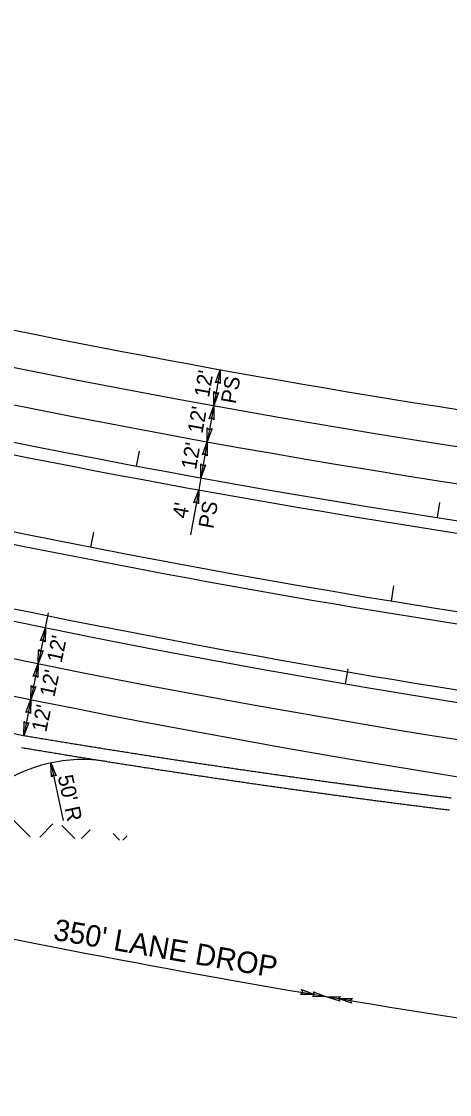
# Model space of a CAD drawing. Extents: x 2389099 to 2405615, y 552200 to 573532.
# Drawn here: x 2399152.7 to 2399293, y 552297.8 to 552649 of the extents above; entities that cross this region are included whole.
import ezdxf

# ---------------------------------------------------------------- set-up
doc = ezdxf.new("R2010")
doc.units = 0
for name, color, linetype in [('Old_Level_22', 7, 'Continuous'), ('Prop Cable Guiderail Double Face', 7, 'Continuous'), ('Prop Dimension', 7, 'Continuous'), ('Prop Dimension Text', 7, 'Continuous'), ('Prop EOT', 7, 'Continuous'), ('Prop Hatching', 7, 'Continuous'), ('Prop Horizontal Alignment', 7, 'Continuous'), ('Prop Horizontal Alignment Tick Small', 7, 'Continuous'), ('Prop Lane Lines', 7, 'Continuous')]:
    doc.layers.add(name, color=color, linetype=linetype)

msp = doc.modelspace()

# ---------------------------------------------------------------- linework, layer by layer
at = {"layer": 'Prop Cable Guiderail Double Face'}
msp.add_arc((2399806.57, 555716.05), 3304, 257.63644, 265.28379, dxfattribs=at)
at = {"layer": 'Prop Dimension'}
for p, q in [((2399217.86, 552535.06), (2399215.75, 552523.25)), ((2399215.75, 552523.25), (2399213.63, 552511.43)), ((2399213.63, 552511.43), (2399211.52, 552499.62)), ((2399211.52, 552499.62), (2399210.81, 552495.68)), ((2399210.81, 552495.68), (2399208.1, 552480.93)), ((2399160.62, 552450.59), (2399158.24, 552438.82)), ((2399158.24, 552438.82), (2399155.86, 552427.06)), ((2399155.86, 552427.06), (2399153.48, 552415.3)), ((2399162.35, 552406.3), (2399166.42, 552387.43))]:
    msp.add_line(p, q, dxfattribs=at)
for points in [[(2399216.3, 552530.77), (2399217.86, 552535.06), (2399217.85, 552530.46), (2399217.16, 552531.17)], [(2399217.3, 552527.54), (2399215.75, 552523.25), (2399215.76, 552527.84), (2399216.44, 552527.13)], [(2399214.19, 552518.95), (2399215.75, 552523.25), (2399215.74, 552518.65), (2399215.05, 552519.36)], [(2399215.19, 552515.73), (2399213.63, 552511.43), (2399213.64, 552516.03), (2399214.33, 552515.32)], [(2399212.08, 552507.14), (2399213.63, 552511.43), (2399213.62, 552506.84), (2399212.94, 552507.55)], [(2399213.08, 552503.91), (2399211.52, 552499.62), (2399211.53, 552504.22), (2399212.22, 552503.51)], [(2399209.24, 552491.4), (2399210.81, 552495.68), (2399210.78, 552491.09), (2399210.1, 552491.8)], [(2399158.97, 552446.33), (2399160.62, 552450.59), (2399160.51, 552445.99), (2399159.84, 552446.71)], [(2399159.89, 552443.08), (2399158.24, 552438.82), (2399158.35, 552443.42), (2399159.02, 552442.7)], [(2399156.59, 552434.57), (2399158.24, 552438.82), (2399158.13, 552434.23), (2399157.46, 552434.95)], [(2399157.51, 552431.32), (2399155.86, 552427.06), (2399155.97, 552431.66), (2399156.64, 552430.93)], [(2399154.21, 552422.81), (2399155.86, 552427.06), (2399155.75, 552422.47), (2399155.08, 552423.19)], [(2399155.13, 552419.56), (2399153.48, 552415.3), (2399153.59, 552419.9), (2399154.26, 552419.17)], [(2399162.54, 552401.74), (2399162.35, 552406.3), (2399164.09, 552402.04), (2399163.18, 552402.44)], [(2399244.52, 552332.11), (2399248.8, 552330.53), (2399244.2, 552330.57), (2399244.92, 552331.25)], [(2399248.4, 552331.39), (2399252.68, 552329.8), (2399248.09, 552329.84), (2399248.8, 552330.53)], [(2399257, 552328.31), (2399252.68, 552329.8), (2399257.28, 552329.86), (2399256.58, 552329.16)], [(2399260.9, 552327.69), (2399256.58, 552329.16), (2399261.17, 552329.25), (2399260.48, 552328.55)]]:
    msp.add_lwpolyline(points, close=True, dxfattribs=at)
msp.add_arc((2399820.18, 555707.47), 3424.97, 258.5517, 264.5865, dxfattribs=at)
at = {"layer": 'Prop EOT'}
for centre, radius, start, end in [((2399792.96, 555724.63), 3253, 240.16192, 265.26734), ((2399792.96, 555724.63), 3241, 256.84167, 265.26734), ((2399820.18, 555707.47), 3359, 249.83254, 258.5517), ((2399792.96, 555724.63), 3281, 256.78262, 265.26734), ((2399820.18, 555707.47), 3319, 256.69858, 263.72436), ((2399172.89, 552357.42), 50, 80.9773, 168.0231)]:
    msp.add_arc(centre, radius, start, end, dxfattribs=at)
for points in [[(2399153.48, 552415.3), (2399154.42, 552415.14), (2399155.36, 552414.99), (2399156.31, 552414.83), (2399157.25, 552414.67), (2399158.19, 552414.51), (2399159.14, 552414.36), (2399160.08, 552414.2), (2399161.03, 552414.05), (2399161.97, 552413.89), (2399162.91, 552413.73), (2399163.86, 552413.58), (2399164.8, 552413.43), (2399165.75, 552413.27), (2399166.69, 552413.12), (2399167.64, 552412.96), (2399168.58, 552412.81), (2399169.52, 552412.65), (2399170.47, 552412.5), (2399171.41, 552412.35), (2399172.36, 552412.2), (2399173.29, 552412.04), (2399174.24, 552411.89), (2399175.19, 552411.74), (2399176.13, 552411.59), (2399177.08, 552411.44), (2399178.02, 552411.29), (2399178.97, 552411.13), (2399179.91, 552410.98), (2399180.85, 552410.83), (2399181.8, 552410.68), (2399182.74, 552410.53), (2399183.69, 552410.38), (2399184.64, 552410.23), (2399185.58, 552410.09), (2399186.53, 552409.94), (2399187.46, 552409.79), (2399188.41, 552409.64), (2399189.36, 552409.49), (2399190.3, 552409.35), (2399191.25, 552409.2), (2399192.19, 552409.05), (2399193.14, 552408.9), (2399194.09, 552408.76), (2399195.03, 552408.61), (2399195.98, 552408.46), (2399196.92, 552408.32), (2399197.86, 552408.17), (2399198.81, 552408.03), (2399199.75, 552407.88), (2399200.7, 552407.74), (2399201.64, 552407.6), (2399202.59, 552407.45), (2399203.54, 552407.31), (2399204.48, 552407.16), (2399205.43, 552407.02), (2399206.37, 552406.88), (2399207.32, 552406.73), (2399208.26, 552406.59), (2399209.21, 552406.45), (2399210.16, 552406.31), (2399211.1, 552406.17), (2399212.05, 552406.03), (2399212.99, 552405.89), (2399213.94, 552405.74), (2399214.89, 552405.6), (2399215.83, 552405.46), (2399216.78, 552405.32), (2399217.72, 552405.18), (2399218.67, 552405.04), (2399219.62, 552404.9), (2399220.56, 552404.77), (2399221.51, 552404.63), (2399222.45, 552404.49), (2399223.4, 552404.35)], [(2399152.82, 552411.36), (2399153.76, 552411.2), (2399154.7, 552411.04), (2399155.65, 552410.88), (2399156.59, 552410.73), (2399157.54, 552410.57), (2399158.49, 552410.41), (2399159.43, 552410.26), (2399160.38, 552410.1), (2399161.32, 552409.94), (2399162.27, 552409.79), (2399163.21, 552409.63), (2399164.15, 552409.48), (2399165.1, 552409.32), (2399166.04, 552409.17), (2399166.99, 552409.01), (2399167.94, 552408.86), (2399168.88, 552408.71), (2399169.83, 552408.55), (2399170.77, 552408.4), (2399171.72, 552408.25), (2399172.66, 552408.09), (2399173.61, 552407.94), (2399174.56, 552407.79), (2399175.5, 552407.64), (2399176.45, 552407.49), (2399177.39, 552407.34), (2399178.33, 552407.18), (2399179.29, 552407.03), (2399180.23, 552406.88), (2399181.18, 552406.73), (2399182.12, 552406.58), (2399183.06, 552406.43), (2399184.01, 552406.28), (2399184.95, 552406.14), (2399185.9, 552405.99), (2399186.84, 552405.84), (2399187.79, 552405.69), (2399188.75, 552405.54), (2399189.69, 552405.39), (2399190.64, 552405.25), (2399191.58, 552405.1), (2399192.52, 552404.95), (2399193.48, 552404.8), (2399194.42, 552404.66), (2399195.37, 552404.51), (2399196.31, 552404.37), (2399197.26, 552404.22), (2399198.21, 552404.07), (2399199.15, 552403.93), (2399200.1, 552403.79), (2399201.04, 552403.64), (2399201.99, 552403.5), (2399202.94, 552403.35), (2399203.88, 552403.21), (2399204.83, 552403.07), (2399205.77, 552402.92), (2399206.72, 552402.78), (2399207.66, 552402.64), (2399208.61, 552402.49), (2399209.56, 552402.35), (2399210.51, 552402.21), (2399211.46, 552402.07), (2399212.4, 552401.93), (2399213.35, 552401.79), (2399214.3, 552401.65), (2399215.24, 552401.51), (2399216.19, 552401.37), (2399217.13, 552401.23), (2399218.08, 552401.09), (2399219.03, 552400.95), (2399219.98, 552400.81), (2399220.93, 552400.67), (2399221.87, 552400.53), (2399222.82, 552400.39)], [(2399223.4, 552404.35), (2399224.35, 552404.21), (2399225.29, 552404.08), (2399226.24, 552403.94), (2399227.18, 552403.8), (2399228.13, 552403.66), (2399229.08, 552403.53), (2399230.02, 552403.39), (2399230.97, 552403.25), (2399231.91, 552403.12), (2399232.86, 552402.98), (2399233.81, 552402.85), (2399234.75, 552402.71), (2399235.7, 552402.58), (2399236.64, 552402.45), (2399237.59, 552402.31), (2399238.54, 552402.18), (2399239.48, 552402.04), (2399240.43, 552401.91), (2399241.37, 552401.78), (2399242.32, 552401.65), (2399243.27, 552401.51), (2399244.22, 552401.38), (2399245.17, 552401.25), (2399246.11, 552401.12), (2399247.06, 552400.99), (2399248, 552400.86), (2399248.95, 552400.72), (2399249.9, 552400.59), (2399250.84, 552400.46), (2399251.79, 552400.33), (2399252.73, 552400.2), (2399253.68, 552400.07), (2399254.64, 552399.94), (2399255.58, 552399.82), (2399256.53, 552399.69), (2399257.47, 552399.56), (2399258.42, 552399.43), (2399259.37, 552399.3), (2399260.31, 552399.18), (2399261.26, 552399.05), (2399262.21, 552398.92), (2399263.16, 552398.79), (2399264.11, 552398.67), (2399265.05, 552398.54), (2399266, 552398.42), (2399266.94, 552398.29), (2399267.89, 552398.17), (2399268.84, 552398.04), (2399269.79, 552397.92), (2399270.74, 552397.79), (2399271.68, 552397.67), (2399272.63, 552397.54), (2399273.58, 552397.42), (2399274.52, 552397.3), (2399275.48, 552397.17), (2399276.42, 552397.05), (2399277.37, 552396.93), (2399278.31, 552396.8), (2399279.26, 552396.68), (2399280.21, 552396.56), (2399281.16, 552396.44), (2399282.11, 552396.32), (2399283.05, 552396.2), (2399284, 552396.08), (2399284.95, 552395.95), (2399285.9, 552395.84), (2399286.85, 552395.71), (2399287.79, 552395.6), (2399288.74, 552395.48), (2399289.69, 552395.36), (2399290.64, 552395.24), (2399291.59, 552395.12), (2399292.53, 552395), (2399293.48, 552394.88)], [(2399222.82, 552400.39), (2399223.77, 552400.25), (2399224.71, 552400.12), (2399225.66, 552399.98), (2399226.6, 552399.84), (2399227.55, 552399.7), (2399228.51, 552399.57), (2399229.45, 552399.43), (2399230.4, 552399.3), (2399231.34, 552399.16), (2399232.29, 552399.02), (2399233.25, 552398.89), (2399234.19, 552398.75), (2399235.14, 552398.62), (2399236.08, 552398.49), (2399237.03, 552398.35), (2399237.98, 552398.22), (2399238.92, 552398.08), (2399239.88, 552397.95), (2399240.82, 552397.82), (2399241.77, 552397.68), (2399242.71, 552397.55), (2399243.66, 552397.42), (2399244.62, 552397.29), (2399245.56, 552397.16), (2399246.51, 552397.02), (2399247.45, 552396.89), (2399248.4, 552396.76), (2399249.36, 552396.63), (2399250.3, 552396.5), (2399251.25, 552396.37), (2399252.19, 552396.24), (2399253.14, 552396.11), (2399254.1, 552395.98), (2399255.04, 552395.85), (2399255.99, 552395.72), (2399256.93, 552395.6), (2399257.88, 552395.47), (2399258.84, 552395.34), (2399259.78, 552395.21), (2399260.73, 552395.08), (2399261.67, 552394.96), (2399262.63, 552394.83), (2399263.58, 552394.7), (2399264.52, 552394.58), (2399265.47, 552394.45), (2399266.42, 552394.33), (2399267.37, 552394.2), (2399268.32, 552394.07), (2399269.26, 552393.95), (2399270.22, 552393.82), (2399271.16, 552393.7), (2399272.11, 552393.58), (2399273.06, 552393.45), (2399274.01, 552393.33), (2399274.96, 552393.2), (2399275.9, 552393.08), (2399276.86, 552392.96), (2399277.8, 552392.84), (2399278.75, 552392.71), (2399279.71, 552392.59), (2399280.65, 552392.47), (2399281.6, 552392.35), (2399282.54, 552392.23), (2399283.5, 552392.11), (2399284.45, 552391.99), (2399285.39, 552391.87), (2399286.35, 552391.75), (2399287.29, 552391.63), (2399288.24, 552391.51), (2399289.19, 552391.39), (2399290.14, 552391.27), (2399291.09, 552391.15), (2399292.04, 552391.03), (2399292.99, 552390.91)]]:
    msp.add_spline(points, degree=3, dxfattribs=at)
at = {"layer": 'Prop Hatching'}
for p, q in [((2399155.56, 552382.16), (2399149.95, 552387.77)), ((2399158.73, 552382.04), (2399163.03, 552386.34)), ((2399170.24, 552381.62), (2399165.99, 552385.87)), ((2399172.37, 552381.54), (2399175.22, 552384.4)), ((2399184.92, 552381.08), (2399182.82, 552383.19)), ((2399186.01, 552381.04), (2399187.42, 552382.45))]:
    msp.add_line(p, q, dxfattribs=at)
at = {"layer": 'Prop Horizontal Alignment'}
for centre, radius, start, end in [((2399792.96, 555724.63), 3277, 240.16192, 265.26734), ((2399806.57, 555716.05), 3300, 240.14547, 265.28379), ((2399820.18, 555707.47), 3323, 240.12925, 265.30001)]:
    msp.add_arc(centre, radius, start, end, dxfattribs=at)
at = {"layer": 'Prop Horizontal Alignment Tick Small'}
for p, q in [((2399190.46, 552503.49), (2399191.38, 552508.4)), ((2399289.02, 552486.61), (2399289.79, 552491.55)), ((2399175.53, 552476.95), (2399176.48, 552481.85)), ((2399273.95, 552459.31), (2399274.76, 552464.25)), ((2399160.62, 552450.59), (2399161.61, 552455.49)), ((2399258.92, 552432.21), (2399259.76, 552437.14))]:
    msp.add_line(p, q, dxfattribs=at)
at = {"layer": 'Prop Lane Lines'}
for centre, radius, start, end in [((2399792.96, 555724.63), 3265, 240.16192, 265.26734), ((2399820.18, 555707.47), 3335, 240.12925, 265.30001), ((2399820.18, 555707.47), 3347, 240.12925, 265.30001)]:
    msp.add_arc(centre, radius, start, end, dxfattribs=at)

# ---------------------------------------------------------------- texts
at = {"layer": 'Old_Level_22'}
msp.add_text("350' LANE DROP", height=7, rotation=350.2613, dxfattribs=at).set_placement((2399162.9, 552348.46))
at = {"layer": 'Prop Dimension Text'}
for s, rotation, p in [("12'", 79.8554, (2399214.16, 552525.73)), ('PS', 79.8554, (2399222.93, 552523.64)), ("12'", 79.8554, (2399212.04, 552513.91)), ("12'", 79.8554, (2399209.93, 552502.1)), ("4'", 79.5751, (2399207.02, 552486.1)), ('PS', 79.5751, (2399215.56, 552482.76)), ("12'", 78.0848, (2399165.88, 552438.86)), ("12'", 78.0848, (2399163.52, 552427.65)), ("12'", 78.0848, (2399160.86, 552416.2)), ("50' R", 282.1698, (2399164.61, 552401.86))]:
    msp.add_text(s, height=5, rotation=rotation, dxfattribs=at).set_placement(p)

doc.saveas('drawing.dxf')
